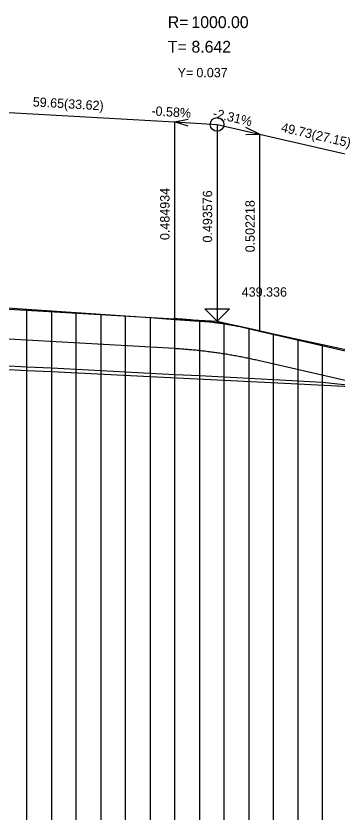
# Model space of a CAD drawing. Extents: x -240 to 1040, y 276 to 593.
# Drawn here: x 457.8 to 523.1, y 404 to 567.4 of the extents above; entities that cross this region are included whole.
import ezdxf

# ---------------------------------------------------------------- set-up
doc = ezdxf.new("R2010")
doc.units = 0
doc.layers.add('1', color=7, linetype='Continuous')
doc.layers.add('2', color=7, linetype='Continuous')

msp = doc.modelspace()

# ---------------------------------------------------------------- linework, layer by layer
at = {"layer": '1'}
for p, q in [((460, 507.74), (455, 508.06)), ((460, 404), (460, 507.74)), ((465, 507.41), (460, 507.74)), ((465, 507.41), (465, 404)), ((470, 507.09), (465, 507.41)), ((470, 404), (470, 507.09)), ((475, 506.74), (470, 507.09)), ((475, 506.74), (475, 404)), ((480, 506.38), (475, 506.74)), ((480, 404), (480, 506.38)), ((485, 506.04), (480, 506.38)), ((485, 506.04), (485, 404)), ((490, 505.66), (485, 506.04)), ((490, 404), (490, 505.66)), ((495, 505.32), (490, 505.66)), ((495, 505.32), (495, 404)), ((500, 504.95), (495, 505.32)), ((500, 404), (500, 504.95)), ((505, 503.88), (500, 504.95)), ((505, 503.88), (505, 404)), ((510, 502.76), (505, 503.88)), ((510, 404), (510, 502.76)), ((515, 501.63), (510, 502.76)), ((515, 501.63), (515, 404)), ((520, 500.56), (515, 501.63)), ((520, 404), (520, 500.56)), ((525, 499.46), (520, 500.56))]:
    msp.add_line(p, q, dxfattribs=at)
at = {"layer": '2'}
for p, q in [((456.32, 547.81), (489.93, 545.86)), ((489.93, 545.86), (492.73, 546.4)), ((489.93, 545.86), (489.93, 505.86)), ((492.73, 545), (489.93, 545.86)), ((489.93, 545.86), (498.58, 545.36)), ((498.58, 545.36), (498.58, 504.99)), ((498.58, 545.36), (507.22, 543.37)), ((507.22, 543.37), (504.42, 544.71)), ((504.42, 543.31), (507.22, 543.37)), ((507.22, 543.37), (507.22, 503.37)), ((507.22, 543.37), (534.36, 537.1)), ((456.32, 507.81), (489.93, 505.86)), ((498.58, 505.36), (496.08, 507.86)), ((496.08, 507.86), (501.08, 507.86)), ((501.08, 507.86), (498.58, 505.36)), ((490.2, 505.85), (489.93, 505.86)), ((489.93, 505.86), (498.58, 505.36)), ((490.47, 505.83), (490.2, 505.85)), ((490.74, 505.81), (490.47, 505.83)), ((491.01, 505.79), (490.74, 505.81)), ((491.28, 505.77), (491.01, 505.79)), ((491.55, 505.75), (491.28, 505.77)), ((491.82, 505.73), (491.55, 505.75)), ((492.09, 505.71), (491.82, 505.73)), ((492.36, 505.69), (492.09, 505.71)), ((492.64, 505.67), (492.36, 505.69)), ((492.91, 505.64), (492.64, 505.67)), ((493.18, 505.62), (492.91, 505.64)), ((493.45, 505.6), (493.18, 505.62)), ((493.72, 505.57), (493.45, 505.6)), ((493.99, 505.54), (493.72, 505.57)), ((494.26, 505.52), (493.99, 505.54)), ((494.53, 505.49), (494.26, 505.52)), ((494.8, 505.46), (494.53, 505.49)), ((495.07, 505.43), (494.8, 505.46)), ((495.34, 505.4), (495.07, 505.43)), ((495.61, 505.37), (495.34, 505.4)), ((495.88, 505.34), (495.61, 505.37)), ((496.15, 505.31), (495.88, 505.34)), ((496.42, 505.28), (496.15, 505.31)), ((496.69, 505.24), (496.42, 505.28)), ((496.96, 505.21), (496.69, 505.24)), ((497.23, 505.17), (496.96, 505.21)), ((497.5, 505.14), (497.23, 505.17)), ((497.77, 505.1), (497.5, 505.14)), ((498.04, 505.06), (497.77, 505.1)), ((498.31, 505.03), (498.04, 505.06)), ((498.58, 504.99), (498.31, 505.03)), ((498.58, 505.36), (507.22, 503.37)), ((498.85, 504.95), (498.58, 504.99)), ((499.12, 504.91), (498.85, 504.95)), ((499.39, 504.87), (499.12, 504.91)), ((499.66, 504.82), (499.39, 504.87)), ((499.93, 504.78), (499.66, 504.82)), ((500.2, 504.74), (499.93, 504.78)), ((500.47, 504.7), (500.2, 504.74)), ((500.74, 504.65), (500.47, 504.7)), ((501.01, 504.61), (500.74, 504.65)), ((501.28, 504.56), (501.01, 504.61)), ((501.55, 504.51), (501.28, 504.56)), ((501.82, 504.47), (501.55, 504.51)), ((502.09, 504.42), (501.82, 504.47)), ((502.36, 504.37), (502.09, 504.42)), ((502.63, 504.32), (502.36, 504.37)), ((502.9, 504.27), (502.63, 504.32)), ((503.17, 504.22), (502.9, 504.27)), ((503.44, 504.17), (503.17, 504.22)), ((503.71, 504.11), (503.44, 504.17)), ((503.98, 504.06), (503.71, 504.11)), ((504.25, 504.01), (503.98, 504.06)), ((504.52, 503.95), (504.25, 504.01)), ((504.79, 503.9), (504.52, 503.95)), ((505.06, 503.84), (504.79, 503.9)), ((505.33, 503.78), (505.06, 503.84)), ((505.6, 503.73), (505.33, 503.78)), ((505.87, 503.67), (505.6, 503.73)), ((506.14, 503.61), (505.87, 503.67)), ((506.41, 503.55), (506.14, 503.61)), ((506.68, 503.49), (506.41, 503.55)), ((506.95, 503.43), (506.68, 503.49)), ((507.22, 503.37), (506.95, 503.43)), ((507.22, 503.37), (534.36, 497.1)), ((456.32, 501.81), (489.93, 499.86)), ((489.93, 499.86), (490.2, 499.85)), ((490.2, 499.85), (490.47, 499.83)), ((490.47, 499.83), (490.74, 499.81)), ((490.74, 499.81), (491.01, 499.79)), ((491.01, 499.79), (491.28, 499.77)), ((491.28, 499.77), (491.55, 499.75)), ((491.55, 499.75), (491.82, 499.73)), ((491.82, 499.73), (492.09, 499.71)), ((492.09, 499.71), (492.36, 499.69)), ((492.36, 499.69), (492.64, 499.67)), ((492.64, 499.67), (492.91, 499.64)), ((492.91, 499.64), (493.18, 499.62)), ((493.18, 499.62), (493.45, 499.6)), ((493.45, 499.6), (493.72, 499.57)), ((493.72, 499.57), (493.99, 499.54)), ((493.99, 499.54), (494.26, 499.52)), ((494.26, 499.52), (494.53, 499.49)), ((494.53, 499.49), (494.8, 499.46)), ((494.8, 499.46), (495.07, 499.43)), ((495.07, 499.43), (495.34, 499.4)), ((495.34, 499.4), (495.61, 499.37)), ((495.61, 499.37), (495.88, 499.34)), ((495.88, 499.34), (496.15, 499.31)), ((496.15, 499.31), (496.42, 499.28)), ((496.42, 499.28), (496.69, 499.24)), ((496.69, 499.24), (496.96, 499.21)), ((496.96, 499.21), (497.23, 499.17)), ((497.23, 499.17), (497.5, 499.14)), ((497.5, 499.14), (497.77, 499.1)), ((497.77, 499.1), (498.04, 499.06)), ((498.04, 499.06), (498.31, 499.03)), ((498.31, 499.03), (498.58, 498.99)), ((498.58, 498.99), (498.85, 498.95)), ((498.85, 498.95), (499.12, 498.91)), ((499.12, 498.91), (499.39, 498.87)), ((499.39, 498.87), (499.66, 498.82)), ((499.66, 498.82), (499.93, 498.78)), ((499.93, 498.78), (500.2, 498.74)), ((500.2, 498.74), (500.47, 498.7)), ((500.47, 498.7), (500.74, 498.65)), ((500.74, 498.65), (501.01, 498.61)), ((501.01, 498.61), (501.28, 498.56)), ((501.28, 498.56), (501.55, 498.51)), ((501.55, 498.51), (501.82, 498.47)), ((501.82, 498.47), (502.09, 498.42)), ((502.09, 498.42), (502.36, 498.37)), ((502.36, 498.37), (502.63, 498.32)), ((502.63, 498.32), (502.9, 498.27)), ((502.9, 498.27), (503.17, 498.22)), ((503.17, 498.22), (503.44, 498.17)), ((503.44, 498.17), (503.71, 498.11)), ((503.71, 498.11), (503.98, 498.06)), ((503.98, 498.06), (504.25, 498.01)), ((504.25, 498.01), (504.52, 497.95)), ((504.52, 497.95), (504.79, 497.9)), ((504.79, 497.9), (505.06, 497.84)), ((505.06, 497.84), (505.33, 497.78)), ((505.33, 497.78), (505.6, 497.73)), ((505.6, 497.73), (505.87, 497.67)), ((505.87, 497.67), (506.14, 497.61)), ((506.14, 497.61), (506.41, 497.55)), ((506.41, 497.55), (506.68, 497.49)), ((506.68, 497.49), (506.95, 497.43)), ((506.95, 497.43), (507.22, 497.37)), ((507.22, 497.37), (534.36, 491.1))]:
    msp.add_line(p, q, dxfattribs=at)
for points in [[(455, 496.38), (460, 496.12), (465, 495.86), (470, 495.6), (475, 495.34), (480, 495.08), (485, 494.82), (490, 494.56), (495, 494.3), (500, 494.04), (505, 493.78), (510, 493.52), (515, 493.26), (520, 493), (525, 492.4)], [(455, 495.63), (460, 495.38), (465, 495.13), (485, 494.12), (500, 493.37), (515, 492.61), (535, 491.6)]]:
    msp.add_lwpolyline(points, dxfattribs=at)
msp.add_circle((498.58, 545.36), 1.4, dxfattribs=at)

# ---------------------------------------------------------------- texts
for s, height, p in [('R=', 2.4, (488.58, 564.95)), ('1000.00', 2.4, (493.38, 564.95)), ('T=', 2.4, (488.58, 559.95)), ('8.642', 2.4, (493.38, 559.95)), ('Y=', 1.9, (490.58, 554.95)), ('0.037', 1.9, (494.38, 554.95)), ('439.336', 1.9, (503.58, 510.36))]:
    msp.add_text(s, height=height, dxfattribs=at).set_placement(p)
for s, rotation, p in [('59.65(33.62)', 356.6804, (461.13, 549.03)), (' -0.58%', 356.6804, (484.5, 547.23)), (' -2.31%', 347.0018, (496.9, 546.95)), ('49.73(27.15)', 347.0018, (511.44, 543.91)), ('0.484934', 90, (488.93, 521.86)), ('0.493576', 90, (497.58, 521.36)), ('0.502218', 90, (506.22, 519.37))]:
    msp.add_text(s, height=1.9, rotation=rotation, dxfattribs=at).set_placement(p)

doc.saveas('drawing.dxf')
